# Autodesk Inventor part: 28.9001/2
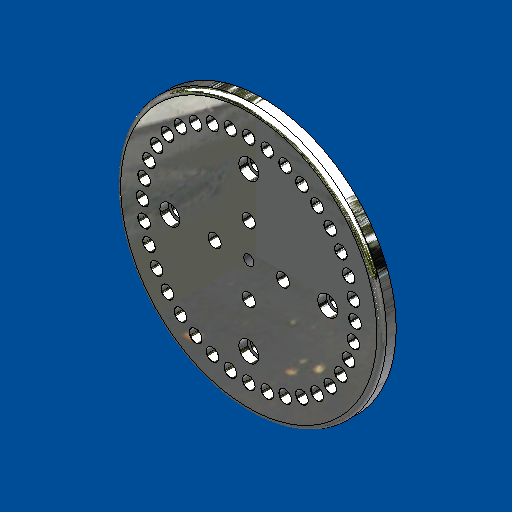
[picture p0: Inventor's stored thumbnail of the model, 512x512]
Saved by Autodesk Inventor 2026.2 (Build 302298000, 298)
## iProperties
Created: 2025-10
Part Number: 28.9001/2
Material: Aluminum 6061
Document SubType Name: Modeling
Designer: amoles
Density: 2.7 g/cm^3
Appearance: Aluminum - Flat
Stock Number: ALUMINUM 6061
Mass: 551.179 g
Surface Area: 591.105 cm^2
Volume: 204.14 cm^3
Vendor: F
Description: SPRING PLUNGER CATCH DISC
FINISH: ETCH & CLEAR ANODIZE
Author: amoles
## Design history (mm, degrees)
sketch "Sketch1"
  geometry: C1 r 87.5 at (0, 0); 1 further point
  constraints: 1 centre point, 1 coincident
  dimensions: "d0" = 175 diameter of C1
extrude "Extrusion1" new body sketch "Sketch1" distance "d1" = 9.525; taper "d2" = 0 deg
sketch "Sketch3"
  geometry: C1 r 87.5 at (0, 0) reference; 2 further points
  constraints: 1 vertical alignment
  dimensions: "d39" = 52 distance of point (0, -52) C1.centre
hole "Hole1" sketch "Sketch3" at (0, -52) diameter "d7" = 8.5; stored, may be unused: countersink angle "d11" = 90 deg, drill point angle "d13" = 118 deg; dims "d8" = 19.05, "d9" = 13, "d10" = 5.5, "d12" = 25.4
sketch "Sketch4"
  geometry: C1 r 87.5 at (0, 0) reference; 2 further points
  constraints: 1 vertical alignment
  dimensions: "d43" = 70 distance of point (0, 70) C1.centre
hole "Hole2" sketch "Sketch4" at (0, 70) diameter "d18" = 8.0899; stored, may be unused: countersink angle "d22" = 90 deg, drill point angle "d24" = 118 deg; dims "d19" = 19.05, "d20" = 8.25, "d21" = 6.35, "d23" = 25.4
pattern_circular "Circular Pattern3" dims angle "d41" = 360 deg
sketch "Sketch10"
  geometry: C1 r 87.5 at (0, 0) reference; 1 further point
  constraints: 1 coincident
hole "Hole3" sketch "Sketch10" at (0, 0) diameter "d78" = 6.647; stored, may be unused: countersink angle "d82" = 82 deg, drill point angle "d84" = 0 deg; dims "d79" = 16.002, "d80" = 9.525, "d81" = 6.35, "d83" = 22.1996
sketch "Sketch12"
  geometry: C1 r 3.323 at (0, 0) reference; 1 further point
  constraints: 1 vertical alignment
  dimensions: "d85" = 22.5 distance of point (0, -22.5) C1.centre
hole "Hole4" sketch "Sketch12" at (0, -22.5) diameter "d86" = 8.5; stored, may be unused: countersink angle "d90" = 82 deg, drill point angle "d92" = 0 deg; dims "d87" = 19.05, "d88" = 9.525, "d89" = 6.35, "d91" = 25.4
pattern_circular "Circular Pattern5" dims angle "d94" = 360 deg
fillet "Fillet1" dims "d96" = 3.175
body "Solid1"
pattern_circular "Circular Pattern4" dims angle "d45" = 360 deg
